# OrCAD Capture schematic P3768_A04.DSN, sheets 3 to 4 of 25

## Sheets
3 0022_M.2 KEY-M _NVMe_ [B]: size Custom
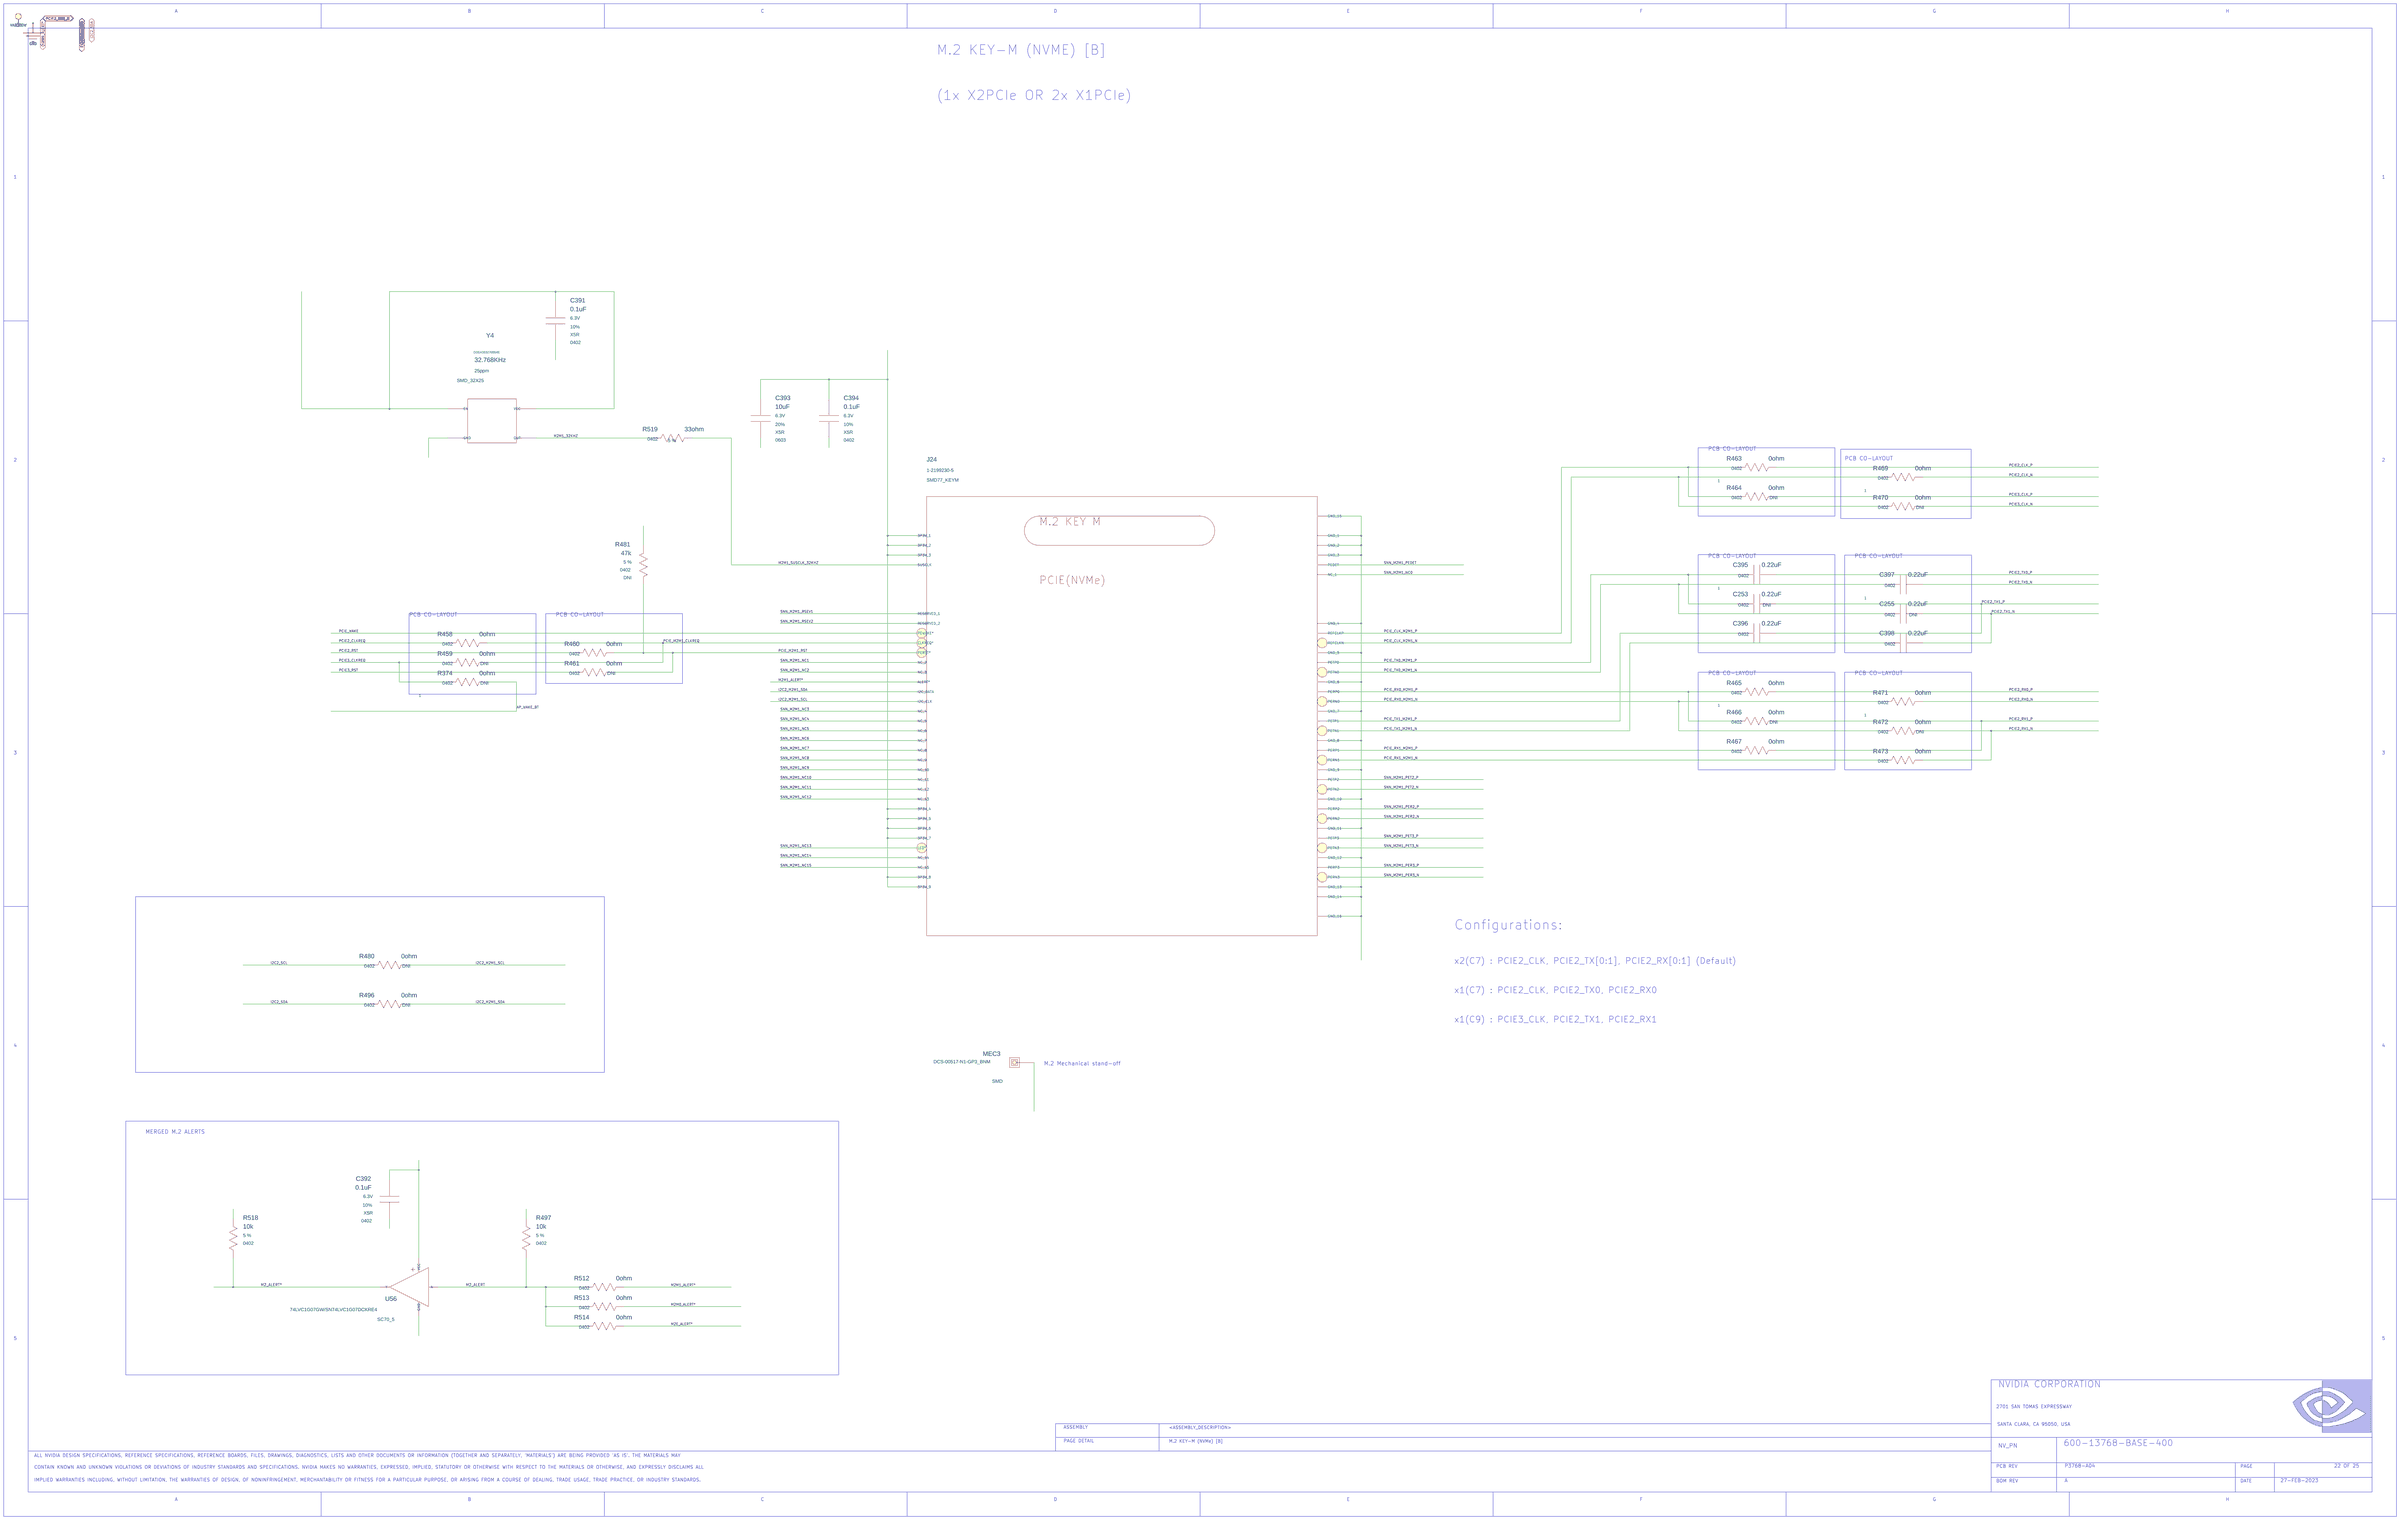
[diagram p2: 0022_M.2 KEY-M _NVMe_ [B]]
4 0021_M.2 KEY-M _NVMe_ [A]: size Custom
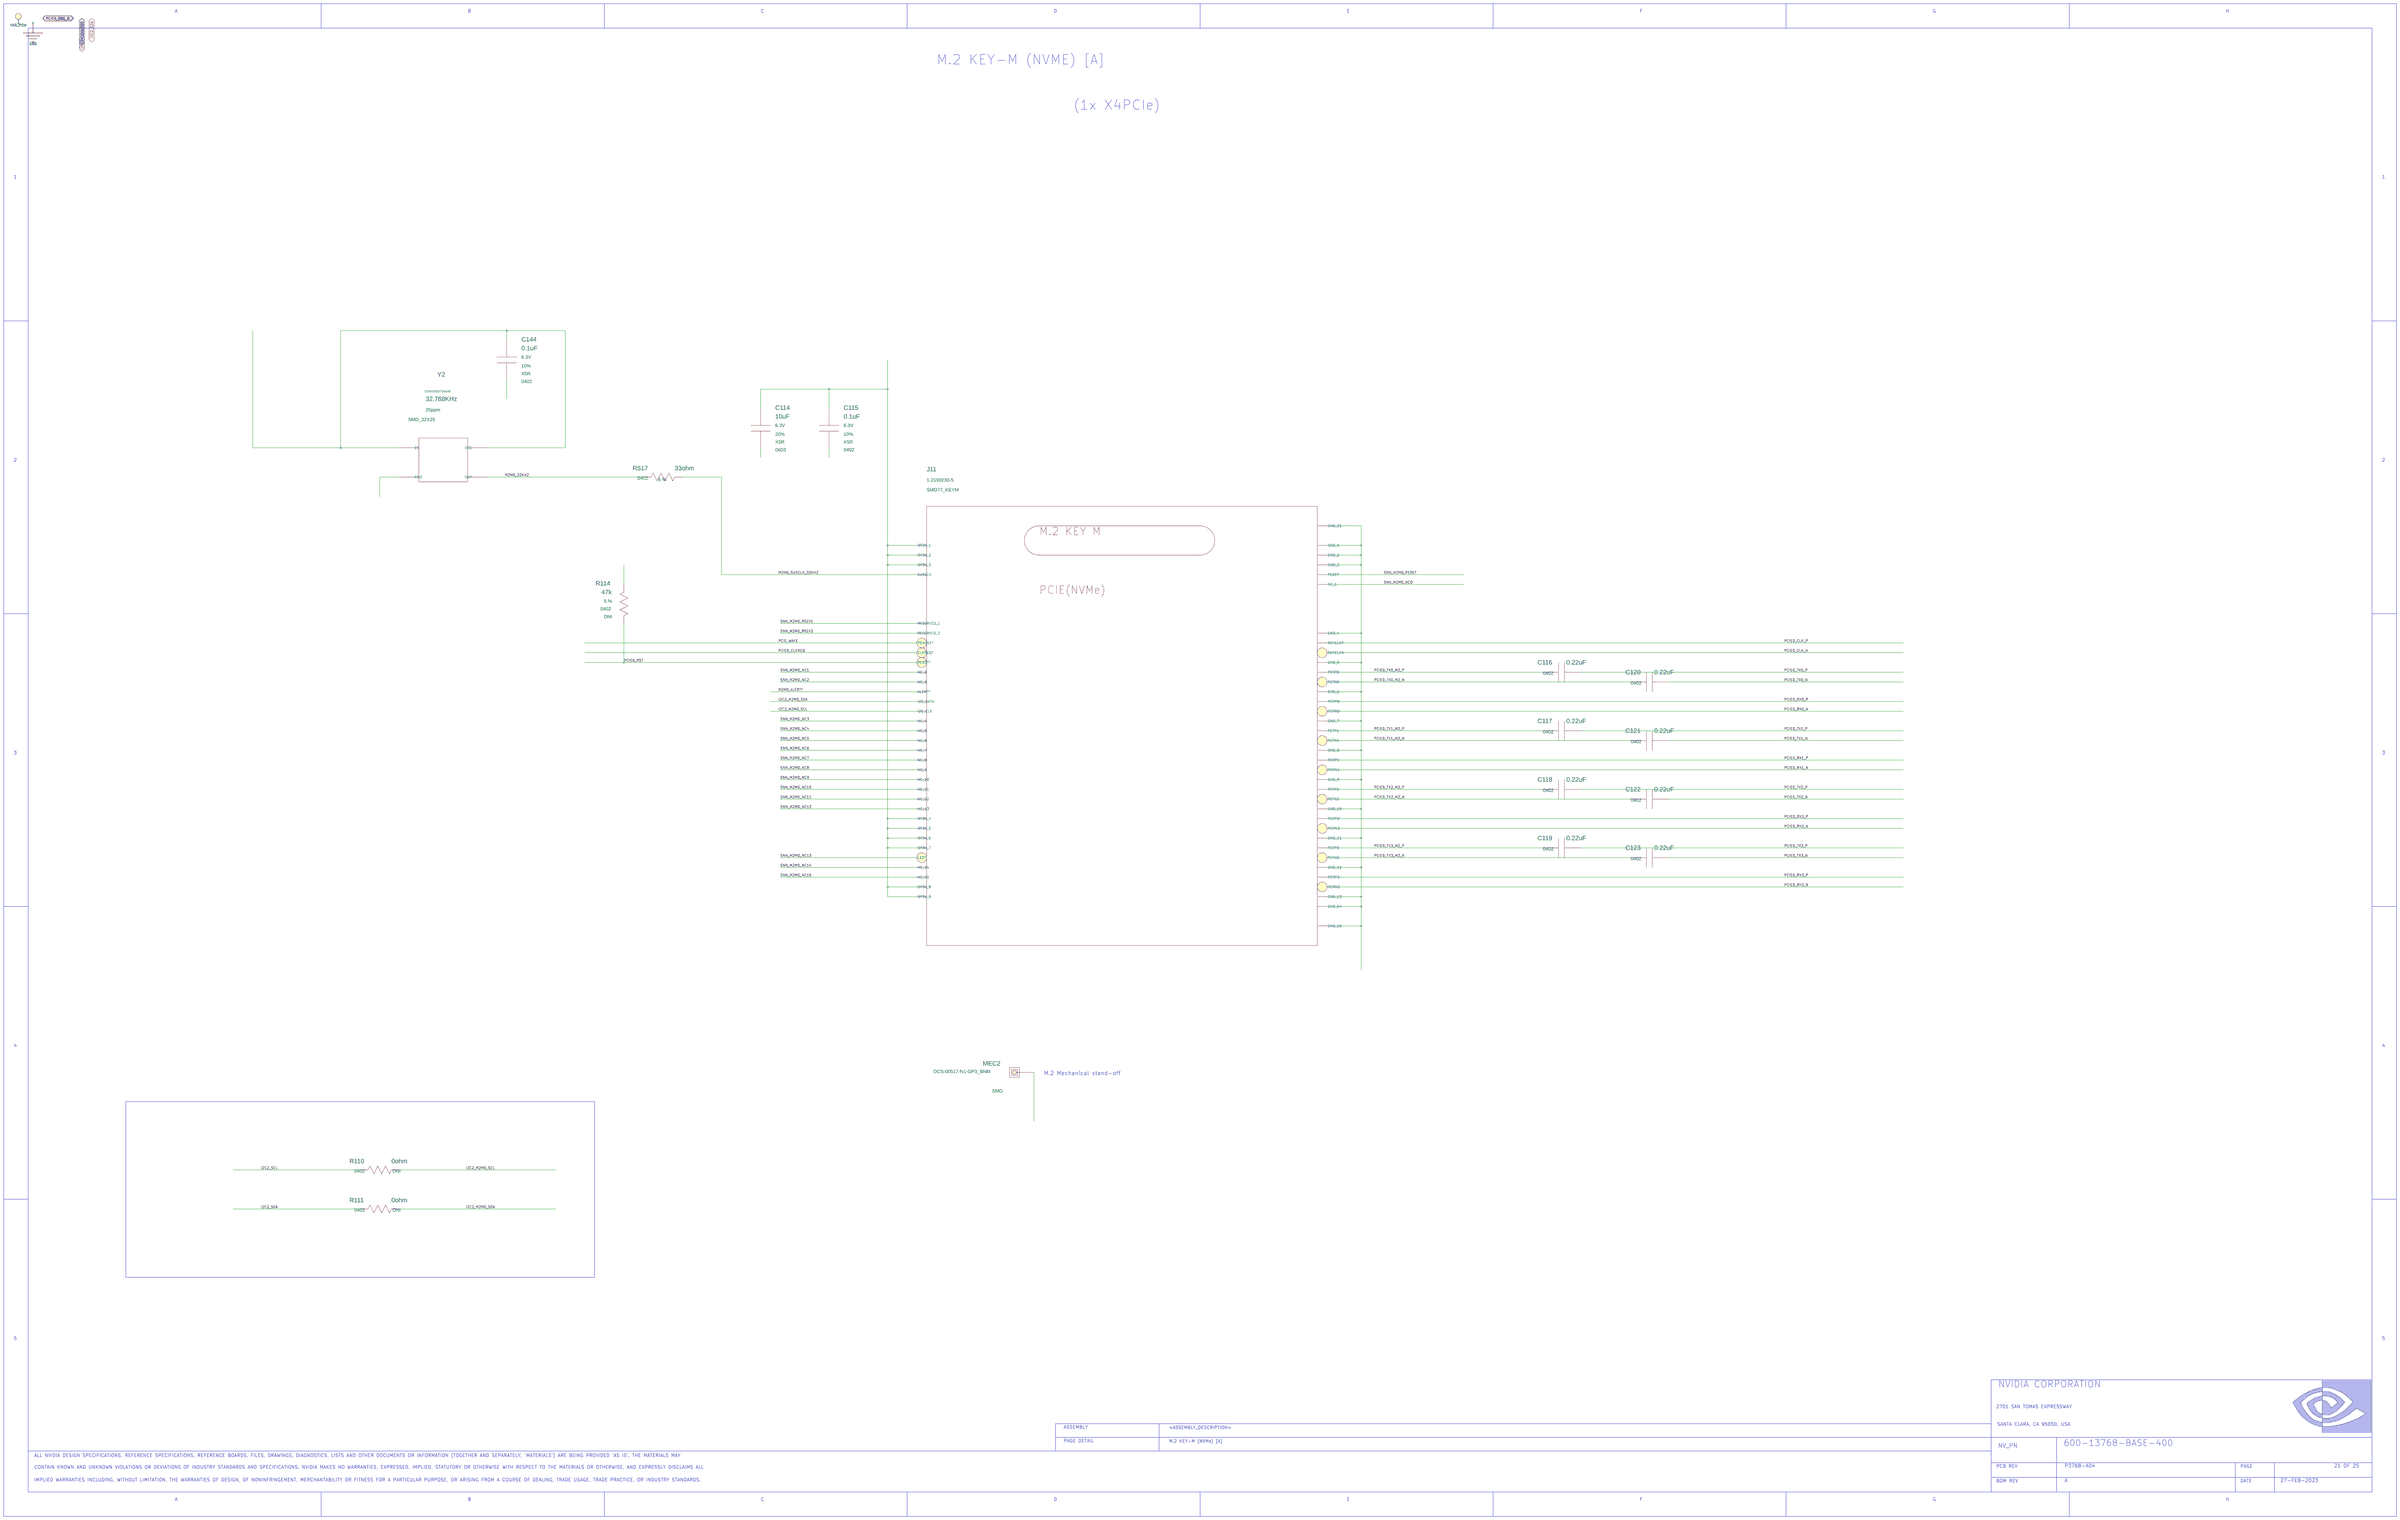
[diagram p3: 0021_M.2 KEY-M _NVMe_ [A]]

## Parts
sheet 0021_M.2 KEY-M _NVMe_ [A]
C114  10uF  [0603]
C115  0.1uF  [0402]
C116  0.22uF  [0402]
C117  0.22uF  [0402]
C118  0.22uF  [0402]
C119  0.22uF  [0402]
C120  0.22uF  [0402]
C121  0.22uF  [0402]
C122  0.22uF  [0402]
C123  0.22uF  [0402]
C144  0.1uF  [0402]
J11  CON_M2_PCI_EXP  [CON_MINIPEX_075_SMT_RA_M2_KEYM_B]
MEC2  MECH_SPECIAL  [MEC_STANDOFF_PTH_620C380P_M3_BNM]
R110  0ohm  [0402]
R111  0ohm  [0402]
R114  47k  [0402]
R517  33ohm  [0402]
Y2  32.768KHz  [XTAL_SMD_4_032X025_D]
sheet 0022_M.2 KEY-M _NVMe_ [B]
C253  0.22uF  [0402]
C255  0.22uF  [0402]
C391  0.1uF  [0402]
C392  0.1uF  [0402]
C393  10uF  [0603]
C394  0.1uF  [0402]
C395  0.22uF  [0402]
C396  0.22uF  [0402]
C397  0.22uF  [0402]
C398  0.22uF  [0402]
J24  CON_M2_PCI_EXP  [CON_MINIPEX_075_SMT_RA_M2_KEYM_B]
MEC3  MECH_SPECIAL  [MEC_STANDOFF_PTH_620C380P_M3_BNM]
R374  0ohm  [0402]
R458  0ohm  [0402]
R459  0ohm  [0402]
R460  0ohm  [0402]
R461  0ohm  [0402]
R463  0ohm  [0402]
R464  0ohm  [0402]
R465  0ohm  [0402]
R466  0ohm  [0402]
R467  0ohm  [0402]
R469  0ohm  [0402]
R470  0ohm  [0402]
R471  0ohm  [0402]
R472  0ohm  [0402]
R473  0ohm  [0402]
R480  0ohm  [0402]
R481  47k  [0402]
R496  0ohm  [0402]
R497  10k  [0402]
R512  0ohm  [0402]
R513  0ohm  [0402]
R514  0ohm  [0402]
R518  10k  [0402]
R519  33ohm  [0402]
U56  U_BUF_OD  [SC70_5]
Y4  32.768KHz  [XTAL_SMD_4_032X025_D]

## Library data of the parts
C114 = C#1: ASSEMBLY: M2_NVME; CDS_LIB: discrete; CDS_PART_NAME: C_0603-10UF,X5R,20%,6.3V,032-2136-000; CDS_PHYS_PART_NAME: C_0603-10UF,X5R,20%,6.3V,032-2136-000-032-2136-000,10UF; CDS_SEC: 1; CHIPS_PART_NAME: C; DEVICE_TYPENAME: C_0603-10UFX5R2063V032-2136-000-032-2136-00010UF; DRAWING: @P3768_A04_LIB.P3768_A04(SCH_1):PAGE21; MAT: X5R; MAX_VOLTAGE: 6.3V; NV_PN: 032-2136-000; PATH: I114; PHYS_PAGE: 21; PSPICETEMPLATE: X^@REFDES  %1    %2   @NV_PN; ROT: 0; SEC: 1; SIGNAL_MODEL: nv_cap; TOL: 20%; VER: 1; XY: (-8250,5450)
C115 = C#1: ASSEMBLY: M2_NVME; CDS_LIB: discrete; CDS_PART_NAME: C_0402-0.1UF,X5R,10%,6.3V,039-0007-000; CDS_PHYS_PART_NAME: C_0402-0.1UF,X5R,10%,6.3V,039-0007-000-0.1UF,039-0007-000; CDS_SEC: 1; CHIPS_PART_NAME: C; DEVICE_TYPENAME: C_0402-01UFX5R1063V039-0007-000-01UF039-0007-000; DRAWING: @P3768_A04_LIB.P3768_A04(SCH_1):PAGE21; MAT: X5R; MAX_VOLTAGE: 6.3V; NV_PN: 039-0007-000; PATH: I116; PHYS_PAGE: 21; PSPICETEMPLATE: X^@REFDES  %1    %2   @NV_PN; ROT: 0; SEC: 1; SIGNAL_MODEL: nv_cap; TOL: 10%; VER: 1; XY: (-7900,5450)
C116 = C: ASSEMBLY: M2_NVME; CDS_LIB: discrete; CDS_PART_NAME: C_0402-0.22UF,X5R,10%,6.3V,039-0011-000; CDS_PHYS_PART_NAME: C_0402-0.22UF,X5R,10%,6.3V,039-0011-000-0.22UF,039-0011-000; CDS_SEC: 1; DEVICE_TYPENAME: C_0402-022UFX5R1063V039-0011-000-022UF039-0011-000; DRAWING: @P3768_A04_LIB.P3768_A04(SCH_1):PAGE21; MAT: X5R; MAX_VOLTAGE: 6.3V; NV_PN: 039-0011-000; PATH: I230; PHYS_PAGE: 21; PSPICETEMPLATE: X^@REFDES  %1    %2   @NV_PN; ROT: 0; SEC: 1; SIGNAL_MODEL: nv_cap; TOL: 10%; VER: 2; XY: (-4150,4200)
C117 = C: ASSEMBLY: M2_NVME; CDS_LIB: discrete; CDS_PART_NAME: C_0402-0.22UF,X5R,10%,6.3V,039-0011-000; CDS_PHYS_PART_NAME: C_0402-0.22UF,X5R,10%,6.3V,039-0011-000-0.22UF,039-0011-000; CDS_SEC: 1; DEVICE_TYPENAME: C_0402-022UFX5R1063V039-0011-000-022UF039-0011-000; DRAWING: @P3768_A04_LIB.P3768_A04(SCH_1):PAGE21; MAT: X5R; MAX_VOLTAGE: 6.3V; NV_PN: 039-0011-000; PATH: I213; PHYS_PAGE: 21; PSPICETEMPLATE: X^@REFDES  %1    %2   @NV_PN; ROT: 0; SEC: 1; SIGNAL_MODEL: nv_cap; TOL: 10%; VER: 2; XY: (-4150,3900)
C118 = C: ASSEMBLY: M2_NVME; CDS_LIB: discrete; CDS_PART_NAME: C_0402-0.22UF,X5R,10%,6.3V,039-0011-000; CDS_PHYS_PART_NAME: C_0402-0.22UF,X5R,10%,6.3V,039-0011-000-0.22UF,039-0011-000; CDS_SEC: 1; DEVICE_TYPENAME: C_0402-022UFX5R1063V039-0011-000-022UF039-0011-000; DRAWING: @P3768_A04_LIB.P3768_A04(SCH_1):PAGE21; MAT: X5R; MAX_VOLTAGE: 6.3V; NV_PN: 039-0011-000; PATH: I212; PHYS_PAGE: 21; PSPICETEMPLATE: X^@REFDES  %1    %2   @NV_PN; ROT: 0; SEC: 1; SIGNAL_MODEL: nv_cap; TOL: 10%; VER: 2; XY: (-4150,3600)
C119 = C: ASSEMBLY: M2_NVME; CDS_LIB: discrete; CDS_PART_NAME: C_0402-0.22UF,X5R,10%,6.3V,039-0011-000; CDS_PHYS_PART_NAME: C_0402-0.22UF,X5R,10%,6.3V,039-0011-000-0.22UF,039-0011-000; CDS_SEC: 1; DEVICE_TYPENAME: C_0402-022UFX5R1063V039-0011-000-022UF039-0011-000; DRAWING: @P3768_A04_LIB.P3768_A04(SCH_1):PAGE21; MAT: X5R; MAX_VOLTAGE: 6.3V; NV_PN: 039-0011-000; PATH: I211; PHYS_PAGE: 21; PSPICETEMPLATE: X^@REFDES  %1    %2   @NV_PN; ROT: 0; SEC: 1; SIGNAL_MODEL: nv_cap; TOL: 10%; VER: 2; XY: (-4150,3300)
C120 = C: ASSEMBLY: M2_NVME; CDS_LIB: discrete; CDS_PART_NAME: C_0402-0.22UF,X5R,10%,6.3V,039-0011-000; CDS_PHYS_PART_NAME: C_0402-0.22UF,X5R,10%,6.3V,039-0011-000-0.22UF,039-0011-000; CDS_SEC: 1; DEVICE_TYPENAME: C_0402-022UFX5R1063V039-0011-000-022UF039-0011-000; DRAWING: @P3768_A04_LIB.P3768_A04(SCH_1):PAGE21; MAT: X5R; MAX_VOLTAGE: 6.3V; NV_PN: 039-0011-000; PATH: I231; PHYS_PAGE: 21; PSPICETEMPLATE: X^@REFDES  %1    %2   @NV_PN; ROT: 0; SEC: 1; SIGNAL_MODEL: nv_cap; TOL: 10%; VER: 2; XY: (-3700,4150)
C121 = C: ASSEMBLY: M2_NVME; CDS_LIB: discrete; CDS_PART_NAME: C_0402-0.22UF,X5R,10%,6.3V,039-0011-000; CDS_PHYS_PART_NAME: C_0402-0.22UF,X5R,10%,6.3V,039-0011-000-0.22UF,039-0011-000; CDS_SEC: 1; DEVICE_TYPENAME: C_0402-022UFX5R1063V039-0011-000-022UF039-0011-000; DRAWING: @P3768_A04_LIB.P3768_A04(SCH_1):PAGE21; MAT: X5R; MAX_VOLTAGE: 6.3V; NV_PN: 039-0011-000; PATH: I216; PHYS_PAGE: 21; PSPICETEMPLATE: X^@REFDES  %1    %2   @NV_PN; ROT: 0; SEC: 1; SIGNAL_MODEL: nv_cap; TOL: 10%; VER: 2; XY: (-3700,3850)
C122 = C: ASSEMBLY: M2_NVME; CDS_LIB: discrete; CDS_PART_NAME: C_0402-0.22UF,X5R,10%,6.3V,039-0011-000; CDS_PHYS_PART_NAME: C_0402-0.22UF,X5R,10%,6.3V,039-0011-000-0.22UF,039-0011-000; CDS_SEC: 1; DEVICE_TYPENAME: C_0402-022UFX5R1063V039-0011-000-022UF039-0011-000; DRAWING: @P3768_A04_LIB.P3768_A04(SCH_1):PAGE21; MAT: X5R; MAX_VOLTAGE: 6.3V; NV_PN: 039-0011-000; PATH: I215; PHYS_PAGE: 21; PSPICETEMPLATE: X^@REFDES  %1    %2   @NV_PN; ROT: 0; SEC: 1; SIGNAL_MODEL: nv_cap; TOL: 10%; VER: 2; XY: (-3700,3550)
C123 = C: ASSEMBLY: M2_NVME; CDS_LIB: discrete; CDS_PART_NAME: C_0402-0.22UF,X5R,10%,6.3V,039-0011-000; CDS_PHYS_PART_NAME: C_0402-0.22UF,X5R,10%,6.3V,039-0011-000-0.22UF,039-0011-000; CDS_SEC: 1; DEVICE_TYPENAME: C_0402-022UFX5R1063V039-0011-000-022UF039-0011-000; DRAWING: @P3768_A04_LIB.P3768_A04(SCH_1):PAGE21; MAT: X5R; MAX_VOLTAGE: 6.3V; NV_PN: 039-0011-000; PATH: I214; PHYS_PAGE: 21; PSPICETEMPLATE: X^@REFDES  %1    %2   @NV_PN; ROT: 0; SEC: 1; SIGNAL_MODEL: nv_cap; TOL: 10%; VER: 2; XY: (-3700,3250)
C144 = C#1: ASSEMBLY: M2_NVME; CDS_LIB: discrete; CDS_PART_NAME: C_0402-0.1UF,X5R,10%,6.3V,039-0007-000; CDS_PHYS_PART_NAME: C_0402-0.1UF,X5R,10%,6.3V,039-0007-000-0.1UF,039-0007-000; CDS_SEC: 1; CHIPS_PART_NAME: C; DEVICE_TYPENAME: C_0402-01UFX5R1063V039-0007-000-01UF039-0007-000; DRAWING: @P3768_A04_LIB.P3768_A04(SCH_1):PAGE21; MAT: X5R; MAX_VOLTAGE: 6.3V; NV_PN: 039-0007-000; PATH: I99; PHYS_PAGE: 21; PSPICETEMPLATE: X^@REFDES  %1    %2   @NV_PN; ROT: 0; SEC: 1; SIGNAL_MODEL: nv_cap; TOL: 10%; VER: 1; XY: (-9550,5800)
J11 = CON_M2_PCI_EXP#1: ANGLE: 90; ASSEMBLY: M2_NVME; CDS_LIB: electro_mechanic; CDS_PART_NAME: CON_M2_PCI_EXP_SMD77_KEYM-1-2199230-5,FEMALE,0.5,90,YES,NO,NO,NO,NO,N/A,N/A,080-1483-000; CDS_PHYS_PART_NAME: CON_M2_PCI_EXP_SMD77_KEYM-1-2199230-5,FEMALE,0.5,90,YES,NO,NO,NO,NO,N/A,N/A,080-1483-000-080-1483-000; CDS_SEC: 1; DEVICE_TYPENAME: CON_M2_PCI_EXP_SMD77_KEYM-1-2199230-5FEMALE0590YESNONONONONANA080-1483-000-080-1483-000; DRAWING: @P3768_A04_LIB.P3768_A04(SCH_1):PAGE21; EMI_GROUND_TAB: No; GENDER: Female; LATCHING: No; MAX_CURRENT: N/A; MAX_VOLTAGE: N/A; NV_NAME: 1-2199230-5; NV_PN: 080-1483-000; PACK_TYPE: SMD77_KEYM; PATH: I240; PHYS_PAGE: 21; PITCH: 0.5; REFLOW: Yes; ROT: 0; SEC: 1; SHIELDED: No; SHROUDED: No; VER: 5; XY: (-6400,3950)
MEC2 = MECH_SPECIAL: ASSEMBLY: M2_NVME; CDS_LIB: mechanic; CDS_PART_NAME: MECH_SPECIAL_SMD-DCS-00517-N1-GP3_BNM,155-0697-000; CDS_PHYS_PART_NAME: MECH_SPECIAL_SMD-DCS-00517-N1-GP3_BNM,155-0697-000-155-0697-000; CDS_SEC: 1; DEVICE_TYPENAME: MECH_SPECIAL_SMD-DCS-00517-N1-GP3_BNM155-0697-000-155-0697-000; DRAWING: @P3768_A04_LIB.P3768_A04(SCH_1):PAGE21; NV_NAME: DCS-00517-N1-GP3_BNM; NV_PN: 155-0697-000; PACK_TYPE: SMD; PATH: I244; PHYS_PAGE: 21; ROT: 2; SEC: 1; VER: 28; XY: (-6950,2150)
R110 = R#1: ASSEMBLY: M2_NVME; CDS_LIB: discrete; CDS_PART_NAME: R_0402-0OHM,0.05 OHM,62.5MW,195-2655-000; CDS_PHYS_PART_NAME: R_0402-0OHM,0.05 OHM,62.5MW,195-2655-000-0OHM,195-2655-000; CDS_SEC: 1; CHIPS_PART_NAME: R; DEVICE_TYPENAME: R_0402-0OHM005OHM625MW195-2655-000-0OHM195-2655-000; DRAWING: @P3768_A04_LIB.P3768_A04(SCH_1):PAGE21; MAX_WATTAGE: 62.5mW; NV_PN: 195-2655-000; PATH: I209; PHYS_PAGE: 21; PSPICETEMPLATE: X^@REFDES  %1    %2   @NV_PN; ROT: 0; SEC: 1; SIGNAL_MODEL: nv_res; SKU: DNI; TOL: 0.05 ohm; VER: 1; XY: (-10200,1650)
R111 = R#1: ASSEMBLY: M2_NVME; CDS_LIB: discrete; CDS_PART_NAME: R_0402-0OHM,0.05 OHM,62.5MW,195-2655-000; CDS_PHYS_PART_NAME: R_0402-0OHM,0.05 OHM,62.5MW,195-2655-000-0OHM,195-2655-000; CDS_SEC: 1; CHIPS_PART_NAME: R; DEVICE_TYPENAME: R_0402-0OHM005OHM625MW195-2655-000-0OHM195-2655-000; DRAWING: @P3768_A04_LIB.P3768_A04(SCH_1):PAGE21; MAX_WATTAGE: 62.5mW; NV_PN: 195-2655-000; PATH: I208; PHYS_PAGE: 21; PSPICETEMPLATE: X^@REFDES  %1    %2   @NV_PN; ROT: 0; SEC: 1; SIGNAL_MODEL: nv_res; SKU: DNI; TOL: 0.05 ohm; VER: 1; XY: (-10200,1450)
R114 = R: ASSEMBLY: M2_NVME; CDS_LIB: discrete; CDS_PART_NAME: R_0402-47K,5 %,62.5MW,195-0599-000; CDS_PHYS_PART_NAME: R_0402-47K,5 %,62.5MW,195-0599-000-195-0599-000,47K; CDS_SEC: 1; DEVICE_TYPENAME: R_0402-47K5625MW195-0599-000-195-0599-00047K; DRAWING: @P3768_A04_LIB.P3768_A04(SCH_1):PAGE21; MAX_WATTAGE: 62.5mW; NV_PN: 195-0599-000; PATH: I104; PHYS_PAGE: 21; PSPICETEMPLATE: X^@REFDES  %1    %2   @NV_PN; ROT: 2; SEC: 1; SIGNAL_MODEL: nv_res; SKU: DNI; TOL: 5 %; VER: 2; XY: (-8950,4550)
R517 = R#1: ASSEMBLY: M2_NVME; CDS_LIB: discrete; CDS_PART_NAME: R_0402-33OHM,5 %,62.5MW,195-0568-000; CDS_PHYS_PART_NAME: R_0402-33OHM,5 %,62.5MW,195-0568-000-195-0568-000,33OHM; CDS_SEC: 1; CHIPS_PART_NAME: R; DEVICE_TYPENAME: R_0402-33OHM5625MW195-0568-000-195-0568-00033OHM; DRAWING: @P3768_A04_LIB.P3768_A04(SCH_1):PAGE21; MAX_WATTAGE: 62.5mW; NV_PN: 195-0568-000; PATH: I242; PHYS_PAGE: 21; ROT: 0; SEC: 1; SIGNAL_MODEL: nv_res; TOL: 5 %; VER: 1; XY: (-8750,5200)
Y2 = OSC_4PIN: ASSEMBLY: M2_NVME; CDS_LIB: clocks; CDS_PART_NAME: OSC_4PIN_SMD_32X25-D3SX003270004E,32.768KHZ,25PPM,3PPM,25PPM,15PF,086-0311-000; CDS_PHYS_PART_NAME: OSC_4PIN_SMD_32X25-D3SX003270004E,32.768KHZ,25PPM,3PPM,25PPM,15PF,086-0311-000-086-0311-000,32.768KHZ; CDS_SEC: 1; DEVICE_TYPENAME: OSC_4PIN_SMD_32X25-D3SX003270004E32768KHZ25PPM3PPM25PPM15PF086-0311-000-086-0311-00032768KHZ; DRAWING: @P3768_A04_LIB.P3768_A04(SCH_1):PAGE21; LOAD_CAPACITANCE: 15pF; NV_NAME: D3SX003270004E; NV_PN: 086-0311-000; PACK_TYPE: SMD_32X25; PATH: I243; PHYS_PAGE: 21; ROT: 0; SEC: 1; TOL: 25ppm; TOL_AGE: 3ppm; TOL_TOTAL: 25ppm; VER: 1; XY: (-9900,5300)
C253 = C: ASSEMBLY: M2M1; CDS_LIB: discrete; CDS_PART_NAME: C_0402-0.22UF,X5R,10%,6.3V,039-0011-000; CDS_PHYS_PART_NAME: C_0402-0.22UF,X5R,10%,6.3V,039-0011-000-0.22UF,039-0011-000; CDS_SEC: 1; DEVICE_TYPENAME: C_0402-022UFX5R1063V039-0011-000-022UF039-0011-000; DRAWING: @P3768_A04_LIB.P3768_A04(SCH_1):PAGE22; MAT: X5R; MAX_VOLTAGE: 6.3V; NO_XNET_CONNECTION: 1; NV_PN: 039-0011-000; PATH: I66; PHYS_PAGE: 22; PSPICETEMPLATE: X^@REFDES  %1    %2   @NV_PN; ROT: 0; SEC: 1; SIGNAL_MODEL: nv_cap; SKU: DNI; TOL: 10%; VER: 2; XY: (-3150,4550)
C255 = C: ASSEMBLY: M2M1; CDS_LIB: discrete; CDS_PART_NAME: C_0402-0.22UF,X5R,10%,6.3V,039-0011-000; CDS_PHYS_PART_NAME: C_0402-0.22UF,X5R,10%,6.3V,039-0011-000-0.22UF,039-0011-000; CDS_SEC: 1; DEVICE_TYPENAME: C_0402-022UFX5R1063V039-0011-000-022UF039-0011-000; DRAWING: @P3768_A04_LIB.P3768_A04(SCH_1):PAGE22; MAT: X5R; MAX_VOLTAGE: 6.3V; NO_XNET_CONNECTION: 1; NV_PN: 039-0011-000; PATH: I70; PHYS_PAGE: 22; PSPICETEMPLATE: X^@REFDES  %1    %2   @NV_PN; ROT: 0; SEC: 1; SIGNAL_MODEL: nv_cap; SKU: DNI; TOL: 10%; VER: 2; XY: (-2400,4500)
C391 = C#1: ASSEMBLY: M2M1; CDS_LIB: discrete; CDS_PART_NAME: C_0402-0.1UF,X5R,10%,6.3V,039-0007-000; CDS_PHYS_PART_NAME: C_0402-0.1UF,X5R,10%,6.3V,039-0007-000-0.1UF,039-0007-000; CDS_SEC: 1; CHIPS_PART_NAME: C; DEVICE_TYPENAME: C_0402-01UFX5R1063V039-0007-000-01UF039-0007-000; DRAWING: @P3768_A04_LIB.P3768_A04(SCH_1):PAGE22; MAT: X5R; MAX_VOLTAGE: 6.3V; NV_PN: 039-0007-000; PATH: I94; PHYS_PAGE: 22; PSPICETEMPLATE: X^@REFDES  %1    %2   @NV_PN; ROT: 0; SEC: 1; SIGNAL_MODEL: nv_cap; TOL: 10%; VER: 1; XY: (-9300,6000)
C392 = C#1: ASSEMBLY: M2M1; CDS_LIB: discrete; CDS_PART_NAME: C_0402-0.1UF,X5R,10%,6.3V,039-0007-000; CDS_PHYS_PART_NAME: C_0402-0.1UF,X5R,10%,6.3V,039-0007-000-0.1UF,039-0007-000; CDS_SEC: 1; CHIPS_PART_NAME: C; DEVICE_TYPENAME: C_0402-01UFX5R1063V039-0007-000-01UF039-0007-000; DRAWING: @P3768_A04_LIB.P3768_A04(SCH_1):PAGE22; MAT: X5R; MAX_VOLTAGE: 6.3V; NV_PN: 039-0007-000; PATH: I132; PHYS_PAGE: 22; ROT: 2; SEC: 1; SIGNAL_MODEL: nv_cap; TOL: 10%; VER: 1; XY: (-10150,1500)
C393 = C#1: ASSEMBLY: M2M1; CDS_LIB: discrete; CDS_PART_NAME: C_0603-10UF,X5R,20%,6.3V,032-2136-000; CDS_PHYS_PART_NAME: C_0603-10UF,X5R,20%,6.3V,032-2136-000-032-2136-000,10UF; CDS_SEC: 1; CHIPS_PART_NAME: C; DEVICE_TYPENAME: C_0603-10UFX5R2063V032-2136-000-032-2136-00010UF; DRAWING: @P3768_A04_LIB.P3768_A04(SCH_1):PAGE22; MAT: X5R; MAX_VOLTAGE: 6.3V; NV_PN: 032-2136-000; PATH: I91; PHYS_PAGE: 22; PSPICETEMPLATE: X^@REFDES  %1    %2   @NV_PN; ROT: 0; SEC: 1; SIGNAL_MODEL: nv_cap; TOL: 20%; VER: 1; XY: (-8250,5500)
C394 = C#1: ASSEMBLY: M2M1; CDS_LIB: discrete; CDS_PART_NAME: C_0402-0.1UF,X5R,10%,6.3V,039-0007-000; CDS_PHYS_PART_NAME: C_0402-0.1UF,X5R,10%,6.3V,039-0007-000-0.1UF,039-0007-000; CDS_SEC: 1; CHIPS_PART_NAME: C; DEVICE_TYPENAME: C_0402-01UFX5R1063V039-0007-000-01UF039-0007-000; DRAWING: @P3768_A04_LIB.P3768_A04(SCH_1):PAGE22; MAT: X5R; MAX_VOLTAGE: 6.3V; NV_PN: 039-0007-000; PATH: I92; PHYS_PAGE: 22; PSPICETEMPLATE: X^@REFDES  %1    %2   @NV_PN; ROT: 0; SEC: 1; SIGNAL_MODEL: nv_cap; TOL: 10%; VER: 1; XY: (-7900,5500)
C395 = C: ASSEMBLY: M2M1; CDS_LIB: discrete; CDS_PART_NAME: C_0402-0.22UF,X5R,10%,6.3V,039-0011-000; CDS_PHYS_PART_NAME: C_0402-0.22UF,X5R,10%,6.3V,039-0011-000-0.22UF,039-0011-000; CDS_SEC: 1; DEVICE_TYPENAME: C_0402-022UFX5R1063V039-0011-000-022UF039-0011-000; DRAWING: @P3768_A04_LIB.P3768_A04(SCH_1):PAGE22; MAT: X5R; MAX_VOLTAGE: 6.3V; NV_PN: 039-0011-000; PATH: I100; PHYS_PAGE: 22; PSPICETEMPLATE: X^@REFDES  %1    %2   @NV_PN; ROT: 0; SEC: 1; SIGNAL_MODEL: nv_cap; TOL: 10%; VER: 2; XY: (-3150,4700)
C396 = C: ASSEMBLY: M2M1; CDS_LIB: discrete; CDS_PART_NAME: C_0402-0.22UF,X5R,10%,6.3V,039-0011-000; CDS_PHYS_PART_NAME: C_0402-0.22UF,X5R,10%,6.3V,039-0011-000-0.22UF,039-0011-000; CDS_SEC: 1; DEVICE_TYPENAME: C_0402-022UFX5R1063V039-0011-000-022UF039-0011-000; DRAWING: @P3768_A04_LIB.P3768_A04(SCH_1):PAGE22; MAT: X5R; MAX_VOLTAGE: 6.3V; NV_PN: 039-0011-000; PATH: I102; PHYS_PAGE: 22; PSPICETEMPLATE: X^@REFDES  %1    %2   @NV_PN; ROT: 0; SEC: 1; SIGNAL_MODEL: nv_cap; TOL: 10%; VER: 2; XY: (-3150,4400)
C397 = C: ASSEMBLY: M2M1; CDS_LIB: discrete; CDS_PART_NAME: C_0402-0.22UF,X5R,10%,6.3V,039-0011-000; CDS_PHYS_PART_NAME: C_0402-0.22UF,X5R,10%,6.3V,039-0011-000-0.22UF,039-0011-000; CDS_SEC: 1; DEVICE_TYPENAME: C_0402-022UFX5R1063V039-0011-000-022UF039-0011-000; DRAWING: @P3768_A04_LIB.P3768_A04(SCH_1):PAGE22; MAT: X5R; MAX_VOLTAGE: 6.3V; NV_PN: 039-0011-000; PATH: I101; PHYS_PAGE: 22; PSPICETEMPLATE: X^@REFDES  %1    %2   @NV_PN; ROT: 0; SEC: 1; SIGNAL_MODEL: nv_cap; TOL: 10%; VER: 2; XY: (-2400,4650)
C398 = C: ASSEMBLY: M2M1; CDS_LIB: discrete; CDS_PART_NAME: C_0402-0.22UF,X5R,10%,6.3V,039-0011-000; CDS_PHYS_PART_NAME: C_0402-0.22UF,X5R,10%,6.3V,039-0011-000-0.22UF,039-0011-000; CDS_SEC: 1; DEVICE_TYPENAME: C_0402-022UFX5R1063V039-0011-000-022UF039-0011-000; DRAWING: @P3768_A04_LIB.P3768_A04(SCH_1):PAGE22; MAT: X5R; MAX_VOLTAGE: 6.3V; NV_PN: 039-0011-000; PATH: I103; PHYS_PAGE: 22; PSPICETEMPLATE: X^@REFDES  %1    %2   @NV_PN; ROT: 0; SEC: 1; SIGNAL_MODEL: nv_cap; TOL: 10%; VER: 2; XY: (-2400,4350)
J24 = CON_M2_PCI_EXP#1: ANGLE: 90; ASSEMBLY: M2M1; CDS_LIB: electro_mechanic; CDS_PART_NAME: CON_M2_PCI_EXP_SMD77_KEYM-1-2199230-5,FEMALE,0.5,90,YES,NO,NO,NO,NO,N/A,N/A,080-1483-000; CDS_PHYS_PART_NAME: CON_M2_PCI_EXP_SMD77_KEYM-1-2199230-5,FEMALE,0.5,90,YES,NO,NO,NO,NO,N/A,N/A,080-1483-000-080-1483-000; CDS_SEC: 1; DEVICE_TYPENAME: CON_M2_PCI_EXP_SMD77_KEYM-1-2199230-5FEMALE0590YESNONONONONANA080-1483-000-080-1483-000; DRAWING: @P3768_A04_LIB.P3768_A04(SCH_1):PAGE22; EMI_GROUND_TAB: No; GENDER: Female; LATCHING: No; MAX_CURRENT: N/A; MAX_VOLTAGE: N/A; NV_NAME: 1-2199230-5; NV_PN: 080-1483-000; PACK_TYPE: SMD77_KEYM; PATH: I114; PHYS_PAGE: 22; PITCH: 0.5; REFLOW: Yes; ROT: 0; SEC: 1; SHIELDED: No; SHROUDED: No; VER: 5; XY: (-6400,4000)
MEC3 = MECH_SPECIAL: ASSEMBLY: M2M1; CDS_LIB: mechanic; CDS_PART_NAME: MECH_SPECIAL_SMD-DCS-00517-N1-GP3_BNM,155-0697-000; CDS_PHYS_PART_NAME: MECH_SPECIAL_SMD-DCS-00517-N1-GP3_BNM,155-0697-000-155-0697-000; CDS_SEC: 1; DEVICE_TYPENAME: MECH_SPECIAL_SMD-DCS-00517-N1-GP3_BNM155-0697-000-155-0697-000; DRAWING: @P3768_A04_LIB.P3768_A04(SCH_1):PAGE22; NV_NAME: DCS-00517-N1-GP3_BNM; NV_PN: 155-0697-000; PACK_TYPE: SMD; PATH: I136; PHYS_PAGE: 22; ROT: 2; SEC: 1; VER: 28; XY: (-6950,2200)
R374 = R#1: ASSEMBLY: M2M1; CDS_LIB: discrete; CDS_PART_NAME: R_0402-0OHM,0.05 OHM,62.5MW,195-2655-000; CDS_PHYS_PART_NAME: R_0402-0OHM,0.05 OHM,62.5MW,195-2655-000-0OHM,195-2655-000; CDS_SEC: 1; CHIPS_PART_NAME: R; DEVICE_TYPENAME: R_0402-0OHM005OHM625MW195-2655-000-0OHM195-2655-000; DRAWING: @P3768_A04_LIB.P3768_A04(SCH_1):PAGE22; MAX_WATTAGE: 62.5mW; NO_XNET_CONNECTION: 1; NV_PN: 195-2655-000; PATH: I107; PHYS_PAGE: 22; ROT: 0; SEC: 1; SIGNAL_MODEL: nv_res; SKU: DNI; TOL: 0.05 ohm; VER: 1; XY: (-9750,4150)
R458 = R#1: ASSEMBLY: M2M1; CDS_LIB: discrete; CDS_PART_NAME: R_0402-0OHM,0.05 OHM,62.5MW,195-2655-000; CDS_PHYS_PART_NAME: R_0402-0OHM,0.05 OHM,62.5MW,195-2655-000-0OHM,195-2655-000; CDS_SEC: 1; CHIPS_PART_NAME: R; DEVICE_TYPENAME: R_0402-0OHM005OHM625MW195-2655-000-0OHM195-2655-000; DRAWING: @P3768_A04_LIB.P3768_A04(SCH_1):PAGE22; MAX_WATTAGE: 62.5mW; NV_PN: 195-2655-000; PATH: I22; PHYS_PAGE: 22; PSPICETEMPLATE: X^@REFDES  %1    %2   @NV_PN; ROT: 0; SEC: 1; SIGNAL_MODEL: nv_res; TOL: 0.05 ohm; VER: 1; XY: (-9750,4350)
R459 = R#1: ASSEMBLY: M2M1; CDS_LIB: discrete; CDS_PART_NAME: R_0402-0OHM,0.05 OHM,62.5MW,195-2655-000; CDS_PHYS_PART_NAME: R_0402-0OHM,0.05 OHM,62.5MW,195-2655-000-0OHM,195-2655-000; CDS_SEC: 1; CHIPS_PART_NAME: R; DEVICE_TYPENAME: R_0402-0OHM005OHM625MW195-2655-000-0OHM195-2655-000; DRAWING: @P3768_A04_LIB.P3768_A04(SCH_1):PAGE22; MAX_WATTAGE: 62.5mW; NV_PN: 195-2655-000; PATH: I21; PHYS_PAGE: 22; PSPICETEMPLATE: X^@REFDES  %1    %2   @NV_PN; ROT: 0; SEC: 1; SIGNAL_MODEL: nv_res; SKU: DNI; TOL: 0.05 ohm; VER: 1; XY: (-9750,4250)
R460 = R#1: ASSEMBLY: M2M1; CDS_LIB: discrete; CDS_PART_NAME: R_0402-0OHM,0.05 OHM,62.5MW,195-2655-000; CDS_PHYS_PART_NAME: R_0402-0OHM,0.05 OHM,62.5MW,195-2655-000-0OHM,195-2655-000; CDS_SEC: 1; CHIPS_PART_NAME: R; DEVICE_TYPENAME: R_0402-0OHM005OHM625MW195-2655-000-0OHM195-2655-000; DRAWING: @P3768_A04_LIB.P3768_A04(SCH_1):PAGE22; MAX_WATTAGE: 62.5mW; NV_PN: 195-2655-000; PATH: I25; PHYS_PAGE: 22; PSPICETEMPLATE: X^@REFDES  %1    %2   @NV_PN; ROT: 0; SEC: 1; SIGNAL_MODEL: nv_res; TOL: 0.05 ohm; VER: 1; XY: (-9100,4300)
R461 = R#1: ASSEMBLY: M2M1; CDS_LIB: discrete; CDS_PART_NAME: R_0402-0OHM,0.05 OHM,62.5MW,195-2655-000; CDS_PHYS_PART_NAME: R_0402-0OHM,0.05 OHM,62.5MW,195-2655-000-0OHM,195-2655-000; CDS_SEC: 1; CHIPS_PART_NAME: R; DEVICE_TYPENAME: R_0402-0OHM005OHM625MW195-2655-000-0OHM195-2655-000; DRAWING: @P3768_A04_LIB.P3768_A04(SCH_1):PAGE22; MAX_WATTAGE: 62.5mW; NV_PN: 195-2655-000; PATH: I26; PHYS_PAGE: 22; PSPICETEMPLATE: X^@REFDES  %1    %2   @NV_PN; ROT: 0; SEC: 1; SIGNAL_MODEL: nv_res; SKU: DNI; TOL: 0.05 ohm; VER: 1; XY: (-9100,4200)
R463 = R#1: ASSEMBLY: M2M1; CDS_LIB: discrete; CDS_PART_NAME: R_0402-0OHM,0.05 OHM,62.5MW,195-2655-000; CDS_PHYS_PART_NAME: R_0402-0OHM,0.05 OHM,62.5MW,195-2655-000-0OHM,195-2655-000; CDS_SEC: 1; CHIPS_PART_NAME: R; DEVICE_TYPENAME: R_0402-0OHM005OHM625MW195-2655-000-0OHM195-2655-000; DRAWING: @P3768_A04_LIB.P3768_A04(SCH_1):PAGE22; MAX_WATTAGE: 62.5mW; NV_PN: 195-2655-000; PATH: I69; PHYS_PAGE: 22; PSPICETEMPLATE: X^@REFDES  %1    %2   @NV_PN; ROT: 0; SEC: 1; SIGNAL_MODEL: nv_res; TOL: 0.05 ohm; VER: 1; XY: (-3150,5250)
R464 = R#1: ASSEMBLY: M2M1; CDS_LIB: discrete; CDS_PART_NAME: R_0402-0OHM,0.05 OHM,62.5MW,195-2655-000; CDS_PHYS_PART_NAME: R_0402-0OHM,0.05 OHM,62.5MW,195-2655-000-0OHM,195-2655-000; CDS_SEC: 1; CHIPS_PART_NAME: R; DEVICE_TYPENAME: R_0402-0OHM005OHM625MW195-2655-000-0OHM195-2655-000; DRAWING: @P3768_A04_LIB.P3768_A04(SCH_1):PAGE22; MAX_WATTAGE: 62.5mW; NO_XNET_CONNECTION: 1; NV_PN: 195-2655-000; PATH: I68; PHYS_PAGE: 22; PSPICETEMPLATE: X^@REFDES  %1    %2   @NV_PN; ROT: 0; SEC: 1; SIGNAL_MODEL: nv_res; SKU: DNI; TOL: 0.05 ohm; VER: 1; XY: (-3150,5100)
R465 = R#1: ASSEMBLY: M2M1; CDS_LIB: discrete; CDS_PART_NAME: R_0402-0OHM,0.05 OHM,62.5MW,195-2655-000; CDS_PHYS_PART_NAME: R_0402-0OHM,0.05 OHM,62.5MW,195-2655-000-0OHM,195-2655-000; CDS_SEC: 1; CHIPS_PART_NAME: R; DEVICE_TYPENAME: R_0402-0OHM005OHM625MW195-2655-000-0OHM195-2655-000; DRAWING: @P3768_A04_LIB.P3768_A04(SCH_1):PAGE22; MAX_WATTAGE: 62.5mW; NV_PN: 195-2655-000; PATH: I61; PHYS_PAGE: 22; PSPICETEMPLATE: X^@REFDES  %1    %2   @NV_PN; ROT: 0; SEC: 1; SIGNAL_MODEL: nv_res; TOL: 0.05 ohm; VER: 1; XY: (-3150,4100)
R466 = R#1: ASSEMBLY: M2M1; CDS_LIB: discrete; CDS_PART_NAME: R_0402-0OHM,0.05 OHM,62.5MW,195-2655-000; CDS_PHYS_PART_NAME: R_0402-0OHM,0.05 OHM,62.5MW,195-2655-000-0OHM,195-2655-000; CDS_SEC: 1; CHIPS_PART_NAME: R; DEVICE_TYPENAME: R_0402-0OHM005OHM625MW195-2655-000-0OHM195-2655-000; DRAWING: @P3768_A04_LIB.P3768_A04(SCH_1):PAGE22; MAX_WATTAGE: 62.5mW; NO_XNET_CONNECTION: 1; NV_PN: 195-2655-000; PATH: I60; PHYS_PAGE: 22; PSPICETEMPLATE: X^@REFDES  %1    %2   @NV_PN; ROT: 0; SEC: 1; SIGNAL_MODEL: nv_res; SKU: DNI; TOL: 0.05 ohm; VER: 1; XY: (-3150,3950)
R467 = R#1: ASSEMBLY: M2M1; CDS_LIB: discrete; CDS_PART_NAME: R_0402-0OHM,0.05 OHM,62.5MW,195-2655-000; CDS_PHYS_PART_NAME: R_0402-0OHM,0.05 OHM,62.5MW,195-2655-000-0OHM,195-2655-000; CDS_SEC: 1; CHIPS_PART_NAME: R; DEVICE_TYPENAME: R_0402-0OHM005OHM625MW195-2655-000-0OHM195-2655-000; DRAWING: @P3768_A04_LIB.P3768_A04(SCH_1):PAGE22; MAX_WATTAGE: 62.5mW; NV_PN: 195-2655-000; PATH: I57; PHYS_PAGE: 22; PSPICETEMPLATE: X^@REFDES  %1    %2   @NV_PN; ROT: 0; SEC: 1; SIGNAL_MODEL: nv_res; TOL: 0.05 ohm; VER: 1; XY: (-3150,3800)
R469 = R#1: ASSEMBLY: M2M1; CDS_LIB: discrete; CDS_PART_NAME: R_0402-0OHM,0.05 OHM,62.5MW,195-2655-000; CDS_PHYS_PART_NAME: R_0402-0OHM,0.05 OHM,62.5MW,195-2655-000-0OHM,195-2655-000; CDS_SEC: 1; CHIPS_PART_NAME: R; DEVICE_TYPENAME: R_0402-0OHM005OHM625MW195-2655-000-0OHM195-2655-000; DRAWING: @P3768_A04_LIB.P3768_A04(SCH_1):PAGE22; MAX_WATTAGE: 62.5mW; NV_PN: 195-2655-000; PATH: I73; PHYS_PAGE: 22; PSPICETEMPLATE: X^@REFDES  %1    %2   @NV_PN; ROT: 0; SEC: 1; SIGNAL_MODEL: nv_res; TOL: 0.05 ohm; VER: 1; XY: (-2400,5200)
R470 = R#1: ASSEMBLY: M2M1; CDS_LIB: discrete; CDS_PART_NAME: R_0402-0OHM,0.05 OHM,62.5MW,195-2655-000; CDS_PHYS_PART_NAME: R_0402-0OHM,0.05 OHM,62.5MW,195-2655-000-0OHM,195-2655-000; CDS_SEC: 1; CHIPS_PART_NAME: R; DEVICE_TYPENAME: R_0402-0OHM005OHM625MW195-2655-000-0OHM195-2655-000; DRAWING: @P3768_A04_LIB.P3768_A04(SCH_1):PAGE22; MAX_WATTAGE: 62.5mW; NO_XNET_CONNECTION: 1; NV_PN: 195-2655-000; PATH: I72; PHYS_PAGE: 22; PSPICETEMPLATE: X^@REFDES  %1    %2   @NV_PN; ROT: 0; SEC: 1; SIGNAL_MODEL: nv_res; SKU: DNI; TOL: 0.05 ohm; VER: 1; XY: (-2400,5050)
R471 = R#1: ASSEMBLY: M2M1; CDS_LIB: discrete; CDS_PART_NAME: R_0402-0OHM,0.05 OHM,62.5MW,195-2655-000; CDS_PHYS_PART_NAME: R_0402-0OHM,0.05 OHM,62.5MW,195-2655-000-0OHM,195-2655-000; CDS_SEC: 1; CHIPS_PART_NAME: R; DEVICE_TYPENAME: R_0402-0OHM005OHM625MW195-2655-000-0OHM195-2655-000; DRAWING: @P3768_A04_LIB.P3768_A04(SCH_1):PAGE22; MAX_WATTAGE: 62.5mW; NV_PN: 195-2655-000; PATH: I65; PHYS_PAGE: 22; PSPICETEMPLATE: X^@REFDES  %1    %2   @NV_PN; ROT: 0; SEC: 1; SIGNAL_MODEL: nv_res; TOL: 0.05 ohm; VER: 1; XY: (-2400,4050)
R472 = R#1: ASSEMBLY: M2M1; CDS_LIB: discrete; CDS_PART_NAME: R_0402-0OHM,0.05 OHM,62.5MW,195-2655-000; CDS_PHYS_PART_NAME: R_0402-0OHM,0.05 OHM,62.5MW,195-2655-000-0OHM,195-2655-000; CDS_SEC: 1; CHIPS_PART_NAME: R; DEVICE_TYPENAME: R_0402-0OHM005OHM625MW195-2655-000-0OHM195-2655-000; DRAWING: @P3768_A04_LIB.P3768_A04(SCH_1):PAGE22; MAX_WATTAGE: 62.5mW; NO_XNET_CONNECTION: 1; NV_PN: 195-2655-000; PATH: I64; PHYS_PAGE: 22; PSPICETEMPLATE: X^@REFDES  %1    %2   @NV_PN; ROT: 0; SEC: 1; SIGNAL_MODEL: nv_res; SKU: DNI; TOL: 0.05 ohm; VER: 1; XY: (-2400,3900)
R473 = R#1: ASSEMBLY: M2M1; CDS_LIB: discrete; CDS_PART_NAME: R_0402-0OHM,0.05 OHM,62.5MW,195-2655-000; CDS_PHYS_PART_NAME: R_0402-0OHM,0.05 OHM,62.5MW,195-2655-000-0OHM,195-2655-000; CDS_SEC: 1; CHIPS_PART_NAME: R; DEVICE_TYPENAME: R_0402-0OHM005OHM625MW195-2655-000-0OHM195-2655-000; DRAWING: @P3768_A04_LIB.P3768_A04(SCH_1):PAGE22; MAX_WATTAGE: 62.5mW; NV_PN: 195-2655-000; PATH: I44; PHYS_PAGE: 22; PSPICETEMPLATE: X^@REFDES  %1    %2   @NV_PN; ROT: 0; SEC: 1; SIGNAL_MODEL: nv_res; TOL: 0.05 ohm; VER: 1; XY: (-2400,3750)
R480 = R#1: ASSEMBLY: M2M1; CDS_LIB: discrete; CDS_PART_NAME: R_0402-0OHM,0.05 OHM,62.5MW,195-2655-000; CDS_PHYS_PART_NAME: R_0402-0OHM,0.05 OHM,62.5MW,195-2655-000-0OHM,195-2655-000; CDS_SEC: 1; CHIPS_PART_NAME: R; DEVICE_TYPENAME: R_0402-0OHM005OHM625MW195-2655-000-0OHM195-2655-000; DRAWING: @P3768_A04_LIB.P3768_A04(SCH_1):PAGE22; MAX_WATTAGE: 62.5mW; NV_PN: 195-2655-000; PATH: I98; PHYS_PAGE: 22; PSPICETEMPLATE: X^@REFDES  %1    %2   @NV_PN; ROT: 0; SEC: 1; SIGNAL_MODEL: nv_res; SKU: DNI; TOL: 0.05 ohm; VER: 1; XY: (-10150,2700)
R481 = R: ASSEMBLY: M2M1; CDS_LIB: discrete; CDS_PART_NAME: R_0402-47K,5 %,62.5MW,195-0599-000; CDS_PHYS_PART_NAME: R_0402-47K,5 %,62.5MW,195-0599-000-195-0599-000,47K; CDS_SEC: 1; DEVICE_TYPENAME: R_0402-47K5625MW195-0599-000-195-0599-00047K; DRAWING: @P3768_A04_LIB.P3768_A04(SCH_1):PAGE22; MAX_WATTAGE: 62.5mW; NV_PN: 195-0599-000; PATH: I27; PHYS_PAGE: 22; PSPICETEMPLATE: X^@REFDES  %1    %2   @NV_PN; ROT: 2; SEC: 1; SIGNAL_MODEL: nv_res; SKU: DNI; TOL: 5 %; VER: 2; XY: (-8850,4750)
R496 = R#1: ASSEMBLY: M2M1; CDS_LIB: discrete; CDS_PART_NAME: R_0402-0OHM,0.05 OHM,62.5MW,195-2655-000; CDS_PHYS_PART_NAME: R_0402-0OHM,0.05 OHM,62.5MW,195-2655-000-0OHM,195-2655-000; CDS_SEC: 1; CHIPS_PART_NAME: R; DEVICE_TYPENAME: R_0402-0OHM005OHM625MW195-2655-000-0OHM195-2655-000; DRAWING: @P3768_A04_LIB.P3768_A04(SCH_1):PAGE22; MAX_WATTAGE: 62.5mW; NV_PN: 195-2655-000; PATH: I99; PHYS_PAGE: 22; PSPICETEMPLATE: X^@REFDES  %1    %2   @NV_PN; ROT: 0; SEC: 1; SIGNAL_MODEL: nv_res; SKU: DNI; TOL: 0.05 ohm; VER: 1; XY: (-10150,2500)
R497 = R: ASSEMBLY: M2M1; CDS_LIB: discrete; CDS_PART_NAME: R_0402-10K,5 %,62.5MW,195-0486-000; CDS_PHYS_PART_NAME: R_0402-10K,5 %,62.5MW,195-0486-000-10K,195-0486-000; CDS_SEC: 1; DEVICE_TYPENAME: R_0402-10K5625MW195-0486-000-10K195-0486-000; DRAWING: @P3768_A04_LIB.P3768_A04(SCH_1):PAGE22; MAX_WATTAGE: 62.5mW; NV_PN: 195-0486-000; PATH: I117; PHYS_PAGE: 22; ROT: 0; SEC: 1; SIGNAL_MODEL: nv_res; TOL: 5 %; VER: 2; XY: (-9450,1300)
R512 = R#1: ASSEMBLY: M2M1; CDS_LIB: discrete; CDS_PART_NAME: R_0402-0OHM,0.05 OHM,62.5MW,195-2655-000; CDS_PHYS_PART_NAME: R_0402-0OHM,0.05 OHM,62.5MW,195-2655-000-0OHM,195-2655-000; CDS_SEC: 1; CHIPS_PART_NAME: R; DEVICE_TYPENAME: R_0402-0OHM005OHM625MW195-2655-000-0OHM195-2655-000; DRAWING: @P3768_A04_LIB.P3768_A04(SCH_1):PAGE22; MAX_WATTAGE: 62.5mW; NV_PN: 195-2655-000; PATH: I124; PHYS_PAGE: 22; PSPICETEMPLATE: X^@REFDES  %1    %2   @NV_PN; ROT: 0; SEC: 1; SIGNAL_MODEL: nv_res; TOL: 0.05 ohm; VER: 1; XY: (-9050,1050)
R513 = R#1: ASSEMBLY: M2M1; CDS_LIB: discrete; CDS_PART_NAME: R_0402-0OHM,0.05 OHM,62.5MW,195-2655-000; CDS_PHYS_PART_NAME: R_0402-0OHM,0.05 OHM,62.5MW,195-2655-000-0OHM,195-2655-000; CDS_SEC: 1; CHIPS_PART_NAME: R; DEVICE_TYPENAME: R_0402-0OHM005OHM625MW195-2655-000-0OHM195-2655-000; DRAWING: @P3768_A04_LIB.P3768_A04(SCH_1):PAGE22; MAX_WATTAGE: 62.5mW; NV_PN: 195-2655-000; PATH: I125; PHYS_PAGE: 22; PSPICETEMPLATE: X^@REFDES  %1    %2   @NV_PN; ROT: 0; SEC: 1; SIGNAL_MODEL: nv_res; TOL: 0.05 ohm; VER: 1; XY: (-9050,950)
R514 = R#1: ASSEMBLY: M2M1; CDS_LIB: discrete; CDS_PART_NAME: R_0402-0OHM,0.05 OHM,62.5MW,195-2655-000; CDS_PHYS_PART_NAME: R_0402-0OHM,0.05 OHM,62.5MW,195-2655-000-0OHM,195-2655-000; CDS_SEC: 1; CHIPS_PART_NAME: R; DEVICE_TYPENAME: R_0402-0OHM005OHM625MW195-2655-000-0OHM195-2655-000; DRAWING: @P3768_A04_LIB.P3768_A04(SCH_1):PAGE22; MAX_WATTAGE: 62.5mW; NV_PN: 195-2655-000; PATH: I126; PHYS_PAGE: 22; PSPICETEMPLATE: X^@REFDES  %1    %2   @NV_PN; ROT: 0; SEC: 1; SIGNAL_MODEL: nv_res; TOL: 0.05 ohm; VER: 1; XY: (-9050,850)
R518 = R: ASSEMBLY: M2M1; CDS_LIB: discrete; CDS_PART_NAME: R_0402-10K,5 %,62.5MW,195-0486-000; CDS_PHYS_PART_NAME: R_0402-10K,5 %,62.5MW,195-0486-000-10K,195-0486-000; CDS_SEC: 1; DEVICE_TYPENAME: R_0402-10K5625MW195-0486-000-10K195-0486-000; DRAWING: @P3768_A04_LIB.P3768_A04(SCH_1):PAGE22; MAX_WATTAGE: 62.5mW; NV_PN: 195-0486-000; PATH: I131; PHYS_PAGE: 22; ROT: 0; SEC: 1; SIGNAL_MODEL: nv_res; TOL: 5 %; VER: 2; XY: (-10950,1300)
R519 = R#1: ASSEMBLY: M2M1; CDS_LIB: discrete; CDS_PART_NAME: R_0402-33OHM,5 %,62.5MW,195-0568-000; CDS_PHYS_PART_NAME: R_0402-33OHM,5 %,62.5MW,195-0568-000-195-0568-000,33OHM; CDS_SEC: 1; CHIPS_PART_NAME: R; DEVICE_TYPENAME: R_0402-33OHM5625MW195-0568-000-195-0568-00033OHM; DRAWING: @P3768_A04_LIB.P3768_A04(SCH_1):PAGE22; MAX_WATTAGE: 62.5mW; NV_PN: 195-0568-000; PATH: I134; PHYS_PAGE: 22; ROT: 0; SEC: 1; SIGNAL_MODEL: nv_res; TOL: 5 %; VER: 1; XY: (-8700,5400)
U56 = U_BUF_OD: ASSEMBLY: M2M1; CDS_LIB: logic; CDS_PART_NAME: U_BUF_OD_SC70_5-74LVC1G07GW/SN74LVC1G07DCKRE4,BUFFER - OPEN DRAIN,115-0138-000; CDS_PHYS_PART_NAME: U_BUF_OD_SC70_5-74LVC1G07GW/SN74LVC1G07DCKRE4,BUFFER - OPEN DRAIN,115-0138-000-115-0138-000; CDS_SEC: 1; DEVICE_TYPENAME: U_BUF_OD_SC70_5-74LVC1G07GWSN74LVC1G07DCKRE4BUFFER-OPENDRAIN115-0138-000-115-0138-000; DRAWING: @P3768_A04_LIB.P3768_A04(SCH_1):PAGE22; FUNCTION: Buffer - Open Drain; NV_NAME: 74LVC1G07GW/SN74LVC1G07DCKRE4; NV_PN: 115-0138-000; PATH: I121; PHYS_PAGE: 22; ROT: 2; SEC: 1; VER: 1; XY: (-10050,1050)
Y4 = OSC_4PIN: ASSEMBLY: M2M1; CDS_LIB: clocks; CDS_PART_NAME: OSC_4PIN_SMD_32X25-D3SX003270004E,32.768KHZ,25PPM,3PPM,25PPM,15PF,086-0311-000; CDS_PHYS_PART_NAME: OSC_4PIN_SMD_32X25-D3SX003270004E,32.768KHZ,25PPM,3PPM,25PPM,15PF,086-0311-000-086-0311-000,32.768KHZ; CDS_SEC: 1; DEVICE_TYPENAME: OSC_4PIN_SMD_32X25-D3SX003270004E32768KHZ25PPM3PPM25PPM15PF086-0311-000-086-0311-00032768KHZ; DRAWING: @P3768_A04_LIB.P3768_A04(SCH_1):PAGE22; LOAD_CAPACITANCE: 15pF; NV_NAME: D3SX003270004E; NV_PN: 086-0311-000; PACK_TYPE: SMD_32X25; PATH: I135; PHYS_PAGE: 22; ROT: 0; SEC: 1; TOL: 25ppm; TOL_AGE: 3ppm; TOL_TOTAL: 25ppm; VER: 1; XY: (-9650,5500)

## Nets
GND: C114.2 C115.2 C144.2 C391.2 C392.2 C393.2 C394.2 J11.1(GND_14) J11.3(GND_13) J11.9(GND_12) J11.15(GND_11) J11.21(GND_10) J11.27(GND_9) J11.33(GND_8) J11.39(GND_7) J11.45(GND_6) J11.51(GND_5) J11.57(GND_4) J11.71(GND_3) J11.73(GND_2) J11.75(GND_1) J11.76(GND_15) J11.77(GND_16) J24.1(GND_14) J24.3(GND_13) J24.9(GND_12) J24.15(GND_11) J24.21(GND_10) J24.27(GND_9) J24.33(GND_8) J24.39(GND_7) J24.45(GND_6) J24.51(GND_5) J24.57(GND_4) J24.71(GND_3) J24.73(GND_2) J24.75(GND_1) J24.76(GND_15) J24.77(GND_16) MEC2.1 MEC3.1 U56.3(GND) Y2.2(GND) Y4.2(GND) ; also on sheet 1 2 5 6 7 8 9 10 11 12 13 14 15 16 17 18 19 21 25
VDD_1V8: C392.1 R497.1 R518.1 U56.5(VCC) ; also on sheet 1 2 5 8 12 14 19 21
VDD_3V3_SYS: C114.1 C115.1 C144.1 C391.1 C393.1 C394.1 J11.2(3P3V_9) J11.4(3P3V_8) J11.12(3P3V_7) J11.14(3P3V_6) J11.16(3P3V_5) J11.18(3P3V_4) J11.70(3P3V_3) J11.72(3P3V_2) J11.74(3P3V_1) J24.2(3P3V_9) J24.4(3P3V_8) J24.12(3P3V_7) J24.14(3P3V_6) J24.16(3P3V_5) J24.18(3P3V_4) J24.70(3P3V_3) J24.72(3P3V_2) J24.74(3P3V_1) R114.1 R481.1 Y2.1(EN) Y2.4(VCC) Y4.1(EN) Y4.4(VCC) ; also on sheet 1 2 5 6 7 8 11 12 14 15 19 20 21
AP_WAKE_BT: R374.2 ; also on sheet 5
I2C2_M2M0_SCL: J11.40(I2C_CLK) R110.2
I2C2_M2M0_SDA: J11.42(I2C_DATA) R111.2
I2C2_M2M1_SCL: J24.40(I2C_CLK) R480.2
I2C2_M2M1_SDA: J24.42(I2C_DATA) R496.2
I2C2_SCL: R110.1 R480.1 ; also on sheet 1 5 21
I2C2_SDA: R111.1 R496.1 ; also on sheet 1 5 21
M2_ALERT: R497.2 R512.1 R513.1 R514.1 U56.2(A)
M2_ALERT*: R518.2 U56.4(Y) ; also on sheet 20
M2E_ALERT*: R514.2 ; also on sheet 5
M2M0_32KHZ: R517.1 Y2.3(OUT)
M2M0_ALERT*: J11.44(ALERT*) R513.2
M2M0_SUSCLK_32KHZ: J11.68(SUSCLK) R517.2
M2M1_32KHZ: R519.1 Y4.3(OUT)
M2M1_ALERT*: J24.44(ALERT*) R512.2
M2M1_SUSCLK_32KHZ: J24.68(SUSCLK) R519.2
PCIE0_CLK_N: J11.53(REFCLKN) ; also on sheet 19
PCIE0_CLK_P: J11.55(REFCLKP) ; also on sheet 19
PCIE0_CLKREQ: J11.52(CLKREQ*) ; also on sheet 19
PCIE0_RST: J11.50(PERST*) R114.2 ; also on sheet 19
PCIE0_RX0_N: J11.41(PERN0) ; also on sheet 19
PCIE0_RX0_P: J11.43(PERP0) ; also on sheet 19
PCIE0_RX1_N: J11.29(PERN1) ; also on sheet 19
PCIE0_RX1_P: J11.31(PERP1) ; also on sheet 19
PCIE0_RX2_N: J11.17(PERN2) ; also on sheet 19
PCIE0_RX2_P: J11.19(PERP2) ; also on sheet 19
PCIE0_RX3_N: J11.5(PERN3) ; also on sheet 19
PCIE0_RX3_P: J11.7(PERP3) ; also on sheet 19
PCIE0_TX0_M2_N: C120.1 J11.47(PETN0)
PCIE0_TX0_M2_P: C116.1 J11.49(PETP0)
PCIE0_TX0_N: C120.2 ; also on sheet 19
PCIE0_TX0_P: C116.2 ; also on sheet 19
PCIE0_TX1_M2_N: C121.1 J11.35(PETN1)
PCIE0_TX1_M2_P: C117.1 J11.37(PETP1)
PCIE0_TX1_N: C121.2 ; also on sheet 19
PCIE0_TX1_P: C117.2 ; also on sheet 19
PCIE0_TX2_M2_N: C122.1 J11.23(PETN2)
PCIE0_TX2_M2_P: C118.1 J11.25(PETP2)
PCIE0_TX2_N: C122.2 ; also on sheet 19
PCIE0_TX2_P: C118.2 ; also on sheet 19
PCIE0_TX3_M2_N: C123.1 J11.11(PETN3)
PCIE0_TX3_M2_P: C119.1 J11.13(PETP3)
PCIE0_TX3_N: C123.2 ; also on sheet 19
PCIE0_TX3_P: C119.2 ; also on sheet 19
PCIE2_CLK_N: R469.2 ; also on sheet 20
PCIE2_CLK_P: R463.2 ; also on sheet 20
PCIE2_CLKREQ: R458.1 ; also on sheet 20
PCIE2_RST: R460.1 ; also on sheet 20
PCIE2_RX0_N: R471.2 ; also on sheet 20
PCIE2_RX0_P: R465.2 ; also on sheet 20
PCIE2_RX1_N: R472.2 R473.2 ; also on sheet 20
PCIE2_RX1_P: R466.2 R467.2 ; also on sheet 20
PCIE2_TX0_N: C397.2 ; also on sheet 20
PCIE2_TX0_P: C395.2 ; also on sheet 20
PCIE2_TX1_N: C255.2 C398.2 ; also on sheet 20
PCIE2_TX1_P: C253.2 C396.2 ; also on sheet 20
PCIE3_CLK_N: R470.2 ; also on sheet 20
PCIE3_CLK_P: R464.2 ; also on sheet 20
PCIE3_CLKREQ: R374.1 R459.1 ; also on sheet 20
PCIE3_RST: R461.1 ; also on sheet 20
PCIE_CLK_M2M1_N: J24.53(REFCLKN) R469.1 R470.1
PCIE_CLK_M2M1_P: J24.55(REFCLKP) R463.1 R464.1
PCIE_M2M1_CLKREQ: J24.52(CLKREQ*) R458.2 R459.2
PCIE_M2M1_RST: J24.50(PERST*) R460.2 R461.2 R481.2
PCIE_RX0_M2M1_N: J24.41(PERN0) R471.1 R472.1
PCIE_RX0_M2M1_P: J24.43(PERP0) R465.1 R466.1
PCIE_RX1_M2M1_N: J24.29(PERN1) R473.1
PCIE_RX1_M2M1_P: J24.31(PERP1) R467.1
PCIE_TX0_M2M1_N: C255.1 C397.1 J24.47(PETN0)
PCIE_TX0_M2M1_P: C253.1 C395.1 J24.49(PETP0)
PCIE_TX1_M2M1_N: C398.1 J24.35(PETN1)
PCIE_TX1_M2M1_P: C396.1 J24.37(PETP1)
PCIE_WAKE: J11.54(PEWAKE*) J24.54(PEWAKE*) ; also on sheet 5 19
SNN_M2M0_NC0: J11.67(NC_1)
SNN_M2M0_NC1: J11.48(NC_2)
SNN_M2M0_NC2: J11.46(NC_3)
SNN_M2M0_NC3: J11.38(NC_4)
SNN_M2M0_NC4: J11.36(NC_5)
SNN_M2M0_NC5: J11.34(NC_6)
SNN_M2M0_NC6: J11.32(NC_7)
SNN_M2M0_NC7: J11.30(NC_8)
SNN_M2M0_NC8: J11.28(NC_9)
SNN_M2M0_NC9: J11.26(NC_10)
SNN_M2M0_NC10: J11.24(NC_11)
SNN_M2M0_NC11: J11.22(NC_12)
SNN_M2M0_NC12: J11.20(NC_13)
SNN_M2M0_NC13: J11.10(LED*)
SNN_M2M0_NC14: J11.8(NC_14)
SNN_M2M0_NC15: J11.6(NC_15)
SNN_M2M0_PEDET: J11.69(PEDET)
SNN_M2M0_RSEV1: J11.58(RESERVED_1)
SNN_M2M0_RSEV2: J11.56(RESERVED_2)
SNN_M2M1_NC0: J24.67(NC_1)
SNN_M2M1_NC1: J24.48(NC_2)
SNN_M2M1_NC2: J24.46(NC_3)
SNN_M2M1_NC3: J24.38(NC_4)
SNN_M2M1_NC4: J24.36(NC_5)
SNN_M2M1_NC5: J24.34(NC_6)
SNN_M2M1_NC6: J24.32(NC_7)
SNN_M2M1_NC7: J24.30(NC_8)
SNN_M2M1_NC8: J24.28(NC_9)
SNN_M2M1_NC9: J24.26(NC_10)
SNN_M2M1_NC10: J24.24(NC_11)
SNN_M2M1_NC11: J24.22(NC_12)
SNN_M2M1_NC12: J24.20(NC_13)
SNN_M2M1_NC13: J24.10(LED*)
SNN_M2M1_NC14: J24.8(NC_14)
SNN_M2M1_NC15: J24.6(NC_15)
SNN_M2M1_PEDET: J24.69(PEDET)
SNN_M2M1_PER2_N: J24.17(PERN2)
SNN_M2M1_PER2_P: J24.19(PERP2)
SNN_M2M1_PER3_N: J24.5(PERN3)
SNN_M2M1_PER3_P: J24.7(PERP3)
SNN_M2M1_PET2_N: J24.23(PETN2)
SNN_M2M1_PET2_P: J24.25(PETP2)
SNN_M2M1_PET3_N: J24.11(PETN3)
SNN_M2M1_PET3_P: J24.13(PETP3)
SNN_M2M1_RSEV1: J24.58(RESERVED_1)
SNN_M2M1_RSEV2: J24.56(RESERVED_2)

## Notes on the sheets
sheet 3
- A
- B
- C
- D
- E
- F
- G
- H
- M.2 KEY-M (NVME) [B]
- (1x X2PCIe OR 2x X1PCIe)
- 1
- 1
- PCB CO-LAYOUT
- 2
- PCB CO-LAYOUT
- 2
- PCB CO-LAYOUT
- PCB CO-LAYOUT
- PCB CO-LAYOUT
- PCB CO-LAYOUT
- PCB CO-LAYOUT
- PCB CO-LAYOUT
- 3
- 3
- Configurations:
- x2(C7) : PCIE2_CLK, PCIE2_TX[0:1], PCIE2_RX[0:1] (Default)
- x1(C7) : PCIE2_CLK, PCIE2_TX0, PCIE2_RX0
- x1(C9) : PCIE3_CLK, PCIE2_TX1, PCIE2_RX1
- 4
- 4
- M.2 Mechanical stand-off
- MERGED M.2 ALERTS
- 5
- 5
- NVIDIA CORPORATION
- 2701 SAN TOMAS EXPRESSWAY
- SANTA CLARA, CA 95050, USA
- ASSEMBLY
- <ASSEMBLY_DESCRIPTION>
- PAGE DETAIL
- M.2 KEY-M (NVMe) [B]
- 600-13768-BASE-400
- NV_PN
- ALL NVIDIA DESIGN SPECIFICATIONS, REFERENCE SPECIFICATIONS, REFERENCE BOARDS, FILES, DRAWINGS, DIAGNOSTICS, LISTS AND OTHER DOCUMENTS OR INFORMATION (TOGETHER AND SEPARATELY, 'MATERIALS') ARE BEING PROVIDED 'AS IS'. THE MATERIALS MAY
- P3768-A04
- 22 OF 25
- CONTAIN KNOWN AND UNKNOWN VIOLATIONS OR DEVIATIONS OF INDUSTRY STANDARDS AND SPECIFICATIONS. NVIDIA MAKES NO WARRANTIES, EXPRESSED, IMPLIED, STATUTORY OR OTHERWISE WITH RESPECT TO THE MATERIALS OR OTHERWISE, AND EXPRESSLY DISCLAIMS ALL
- PCB REV
- PAGE
- IMPLIED WARRANTIES INCLUDING, WITHOUT LIMITATION, THE WARRANTIES OF DESIGN, OF NONINFRINGEMENT, MERCHANTABILITY OR FITNESS FOR A PARTICULAR PURPOSE, OR ARISING FROM A COURSE OF DEALING, TRADE USAGE, TRADE PRACTICE, OR INDUSTRY STANDARDS.
- BOM REV
- A
- DATE
- 27-FEB-2023
- A
- B
- C
- D
- E
- F
- G
- H
sheet 4
- A
- B
- C
- D
- E
- F
- G
- H
- M.2 KEY-M (NVME) [A]
- (1x X4PCIe)
- 1
- 1
- 2
- 2
- 3
- 3
- 4
- 4
- M.2 Mechanical stand-off
- 5
- 5
- NVIDIA CORPORATION
- 2701 SAN TOMAS EXPRESSWAY
- SANTA CLARA, CA 95050, USA
- ASSEMBLY
- <ASSEMBLY_DESCRIPTION>
- PAGE DETAIL
- M.2 KEY-M (NVMe) [A]
- 600-13768-BASE-400
- NV_PN
- ALL NVIDIA DESIGN SPECIFICATIONS, REFERENCE SPECIFICATIONS, REFERENCE BOARDS, FILES, DRAWINGS, DIAGNOSTICS, LISTS AND OTHER DOCUMENTS OR INFORMATION (TOGETHER AND SEPARATELY, 'MATERIALS') ARE BEING PROVIDED 'AS IS'. THE MATERIALS MAY
- P3768-A04
- 21 OF 25
- CONTAIN KNOWN AND UNKNOWN VIOLATIONS OR DEVIATIONS OF INDUSTRY STANDARDS AND SPECIFICATIONS. NVIDIA MAKES NO WARRANTIES, EXPRESSED, IMPLIED, STATUTORY OR OTHERWISE WITH RESPECT TO THE MATERIALS OR OTHERWISE, AND EXPRESSLY DISCLAIMS ALL
- PCB REV
- PAGE
- IMPLIED WARRANTIES INCLUDING, WITHOUT LIMITATION, THE WARRANTIES OF DESIGN, OF NONINFRINGEMENT, MERCHANTABILITY OR FITNESS FOR A PARTICULAR PURPOSE, OR ARISING FROM A COURSE OF DEALING, TRADE USAGE, TRADE PRACTICE, OR INDUSTRY STANDARDS.
- BOM REV
- A
- DATE
- 27-FEB-2023
- A
- B
- C
- D
- E
- F
- G
- H
